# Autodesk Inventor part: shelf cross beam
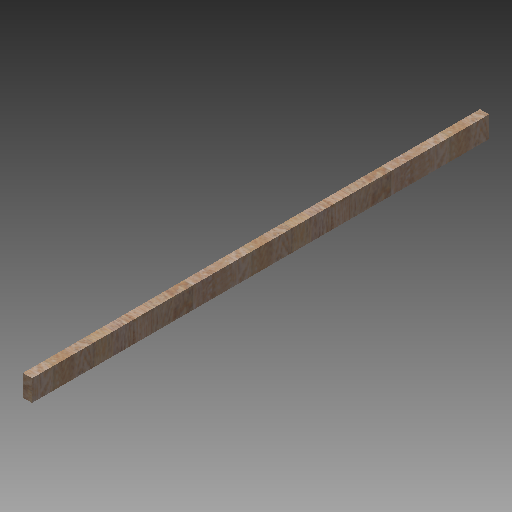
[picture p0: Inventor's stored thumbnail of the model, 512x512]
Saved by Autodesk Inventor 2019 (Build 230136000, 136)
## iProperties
Created: 2013-07
Part Number: shelf cross beam
Material: Generic
Document SubType Name: Modeling
Designer: Patrick Rice
Density: 1 g/cm^3
Appearance: Red Oak - Natural
Author: Patrick Rice
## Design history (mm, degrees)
sketch "Sketch1"
  geometry: L1 (19.05, -44.45)-(-19.05, -44.45); L2 (-19.05, -44.45)-(-19.05, 44.45); L3 (-19.05, 44.45)-(19.05, 44.45); L4 (19.05, 44.45)-(19.05, -44.45); L5 (19.05, -44.45)-(-19.05, 44.45); L6 (-19.05, -44.45)-(19.05, 44.45); 1 further point
  constraints: 12 end point, 2 midpoint, 2 parallel, 1 horizontal, 1 perpendicular
  dimensions: "d0" = 38.1 distance of L2.end L3.end; "d1" = 88.9 distance of L1.end L2.end
extrude "Extrusion1" new body sketch "Sketch1" distance "d2" = 1905; taper "d3" = 0 deg
body "Solid1"
